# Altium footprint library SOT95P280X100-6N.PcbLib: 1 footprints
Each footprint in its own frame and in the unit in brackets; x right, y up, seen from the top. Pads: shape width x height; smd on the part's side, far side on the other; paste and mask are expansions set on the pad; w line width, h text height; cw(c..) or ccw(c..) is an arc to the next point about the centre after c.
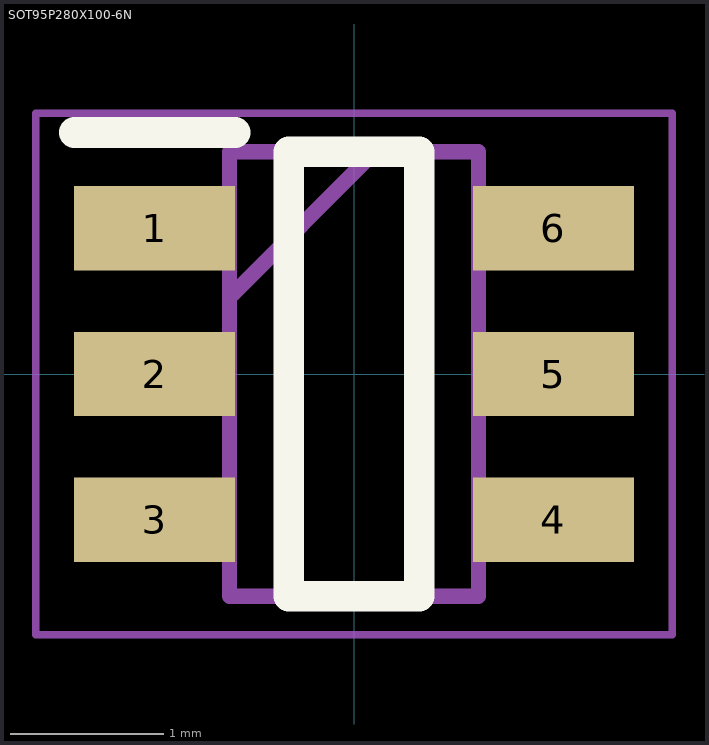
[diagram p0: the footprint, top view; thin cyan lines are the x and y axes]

## SOT95P280X100-6N [mm]
pads (6):
  rect 1.05x0.55 smd: 1(-1.3,0.95) 2(-1.3,0) 3(-1.3,-0.95) 4(1.3,-0.95) 5(1.3,0) 6(1.3,0.95)
Top Overlay:
  lines w0.2: -1.825,1.575 -0.775,1.575 ; -0.425,-1.45 0.425,-1.45 0.425,1.45 -0.425,1.45 -0.425,-1.45
Mechanical 15:
  lines w0.1: -0.812,0.5 0.138,1.45 ; -0.812,-1.45 0.812,-1.45 0.812,1.45 -0.812,1.45 -0.812,-1.45
Mechanical 20:
  lines w0.05: -2.075,-1.7 2.075,-1.7 2.075,1.7 -2.075,1.7 -2.075,-1.7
